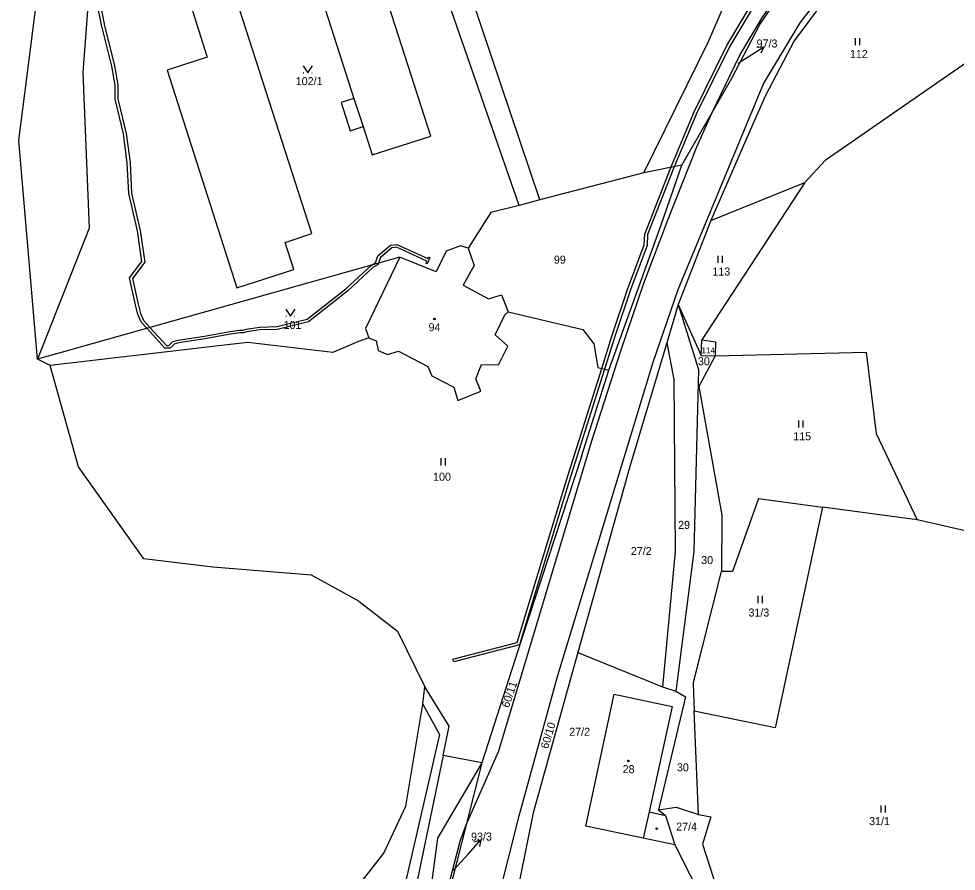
# Model space of a CAD drawing. Extents: x -670359 to -660124, y -978807 to -970072.
# Drawn here: x -670303.1 to -670103.9, y -977465.8 to -977284.7 of the extents above; entities that cross this region are included whole.
import ezdxf

# ---------------------------------------------------------------- set-up
doc = ezdxf.new("R2010")
doc.units = 0
for name, color, linetype in [('Hranice kat_území', 7, 'Continuous'), ('Hranice parcel', 7, 'Continuous'), ('Parcelní čísla', 7, 'Continuous'), ('Vnitřní kresba', 7, 'Continuous'), ('Věcná břemena k části', 7, 'Continuous'), ('Značky budov', 7, 'Continuous'), ('Značky kultur', 7, 'Continuous')]:
    doc.layers.add(name, color=color, linetype=linetype)

msp = doc.modelspace()

# ---------------------------------------------------------------- linework, layer by layer
at = {"layer": 'Hranice kat_území'}
for points in [[(-670303.09, -977310.58), (-670295.8, -977253.36)], [(-670299.11, -977356.99), (-670303.09, -977310.58)], [(-670296.4, -977358.37), (-670299.11, -977356.99)], [(-670290.39, -977379.85), (-670296.4, -977358.37)], [(-670276.51, -977399.38), (-670290.39, -977379.85)], [(-670261.89, -977401.16), (-670276.51, -977399.38)], [(-670240.86, -977402.91), (-670261.89, -977401.16)], [(-670230.82, -977408.42), (-670240.86, -977402.91)], [(-670230.82, -977408.42), (-670222.62, -977414.79)], [(-670222.62, -977414.79), (-670216.78, -977426.59)], [(-670217.21, -977430.27), (-670216.78, -977426.59)], [(-670220.88, -977451.91), (-670217.21, -977430.27)], [(-670225.52, -977461.96), (-670220.88, -977451.91)], [(-670231.74, -977469.91), (-670225.52, -977461.96)]]:
    msp.add_lwpolyline(points, dxfattribs=at)
at = {"layer": 'Hranice parcel'}
for points in [[(-670192.35, -977323.19), (-670223.53, -977230.71)], [(-670196.76, -977324.36), (-670228.36, -977233.44)], [(-670206.03, -977490.9), (-670201.37, -977472.26), (-670196.78, -977453.99), (-670188.6, -977424.41), (-670168.29, -977357.64), (-670162.97, -977342.22), (-670144.87, -977298.55), (-670137.06, -977285.54), (-670128.3, -977274.09), (-670118, -977262.95), (-670116.3, -977261.29)], [(-670215.56, -977309.6), (-670228.65, -977268.92)], [(-670155.78, -977304.6), (-670149.86, -977292.46), (-670145.08, -977284.34), (-670139.87, -977276.96), (-670134.89, -977270.75), (-670132.18, -977267.78)], [(-670122.33, -977267.85), (-670138.33, -977289.41)], [(-670241.01, -977273.11), (-670231.87, -977301.63)], [(-670145.67, -977285.92), (-670138.88, -977275.97)], [(-670240.8, -977330.34), (-670257.55, -977278.44)], [(-670266.7, -977281.45), (-670263.03, -977292.85)], [(-670087.08, -977283.85), (-670131.79, -977314.81)], [(-670151.59, -977297.32), (-670145.67, -977285.92)], [(-670138.33, -977289.41), (-670144.5, -977301.13)], [(-670263.03, -977292.85), (-670271.59, -977295.6)], [(-670271.59, -977295.6), (-670256.75, -977341.84)], [(-670155.78, -977304.6), (-670151.59, -977297.32)], [(-670144.5, -977301.13), (-670148.4, -977309.98)], [(-670231.87, -977301.63), (-670234.57, -977302.49)], [(-670234.57, -977302.49), (-670232.66, -977308.47)], [(-670201.12, -977440.18), (-670181.39, -977374.59), (-670175.18, -977355.21), (-670170.26, -977340.86), (-670165.11, -977327.29), (-670159.02, -977311.91), (-670155.78, -977304.6)], [(-670162.21, -977315.8), (-670155.78, -977304.6)], [(-670232.66, -977308.47), (-670229.95, -977307.6)], [(-670229.95, -977307.6), (-670228.02, -977313.62)], [(-670228.02, -977313.62), (-670215.56, -977309.6)], [(-670148.4, -977309.98), (-670156.05, -977327.52)], [(-670131.79, -977314.81), (-670136.07, -977319.5)], [(-670170.3, -977317.45), (-670192.35, -977323.19)], [(-670162.21, -977315.8), (-670170.3, -977317.45)], [(-670166.62, -977328.49), (-670162.21, -977315.8)], [(-670136.07, -977319.5), (-670157.98, -977352.9)], [(-670156.05, -977327.52), (-670136.07, -977319.5)], [(-670192.35, -977323.19), (-670196.76, -977324.36)], [(-670196.76, -977324.36), (-670202.77, -977325.83)], [(-670202.77, -977325.83), (-670207.63, -977333.4)], [(-670177.7, -977359.35), (-670166.62, -977328.49)], [(-670156.05, -977327.52), (-670162.98, -977345.39)], [(-670246.48, -977332.24), (-670240.8, -977330.34)], [(-670244.64, -977337.96), (-670246.48, -977332.24)], [(-670209.23, -977332.91), (-670212.28, -977334.09)], [(-670207.63, -977333.4), (-670209.23, -977332.91)], [(-670207.63, -977333.4), (-670206.3, -977337.09)], [(-670222.13, -977335.3), (-670299.11, -977356.99)], [(-670222.13, -977335.3), (-670229.44, -977350.52)], [(-670214.39, -977338.47), (-670222.13, -977335.3)], [(-670212.28, -977334.09), (-670214.39, -977338.47)], [(-670206.3, -977337.09), (-670208.65, -977341.31)], [(-670256.75, -977341.84), (-670244.64, -977337.96)], [(-670208.65, -977341.31), (-670203.31, -977344.15)], [(-670203.31, -977344.15), (-670200.5, -977343.37)], [(-670200.5, -977343.37), (-670199.08, -977346.97)], [(-670199.85, -977347.6), (-670199.08, -977346.97)], [(-670199.08, -977346.97), (-670183.27, -977350.68)], [(-670162.98, -977345.39), (-670165.4, -977353.5)], [(-670162.98, -977345.39), (-670158.68, -977359.17)], [(-670162.98, -977345.39), (-670158.11, -977356.19)], [(-670201.84, -977351.83), (-670199.85, -977347.6)], [(-670229.44, -977350.52), (-670228.7, -977352.45)], [(-670183.27, -977350.68), (-670180.89, -977353.74)], [(-670230.9, -977353.23), (-670236.36, -977355.59)], [(-670228.7, -977352.45), (-670230.9, -977353.23)], [(-670228.7, -977352.45), (-670227.14, -977353.1)], [(-670227.14, -977353.1), (-670226.75, -977355.18)], [(-670199.19, -977354.25), (-670201.84, -977351.83)], [(-670158.11, -977356.19), (-670157.98, -977352.9)], [(-670157.98, -977352.9), (-670155.03, -977353.34)], [(-670155.03, -977353.34), (-670155.15, -977356.3)], [(-670260.03, -977354.07), (-670296.4, -977358.37)], [(-670254.43, -977353.47), (-670260.03, -977354.07)], [(-670236.36, -977355.59), (-670254.43, -977353.47)], [(-670226.75, -977355.18), (-670224.76, -977355.99)], [(-670224.76, -977355.99), (-670222.43, -977355.29)], [(-670222.43, -977355.29), (-670216.21, -977358.53)], [(-670201.16, -977358.18), (-670199.19, -977354.25)], [(-670180.89, -977353.74), (-670180.04, -977358.78)], [(-670165.4, -977353.5), (-670173.4, -977380.26)], [(-670165.4, -977353.5), (-670163.9, -977361.3)], [(-670155.15, -977356.3), (-670158.63, -977362.77)], [(-670158.11, -977356.19), (-670155.15, -977356.3)], [(-670155.15, -977356.3), (-670123.04, -977355.5)], [(-670123.04, -977355.5), (-670120.93, -977372.79)], [(-670216.21, -977358.53), (-670215.35, -977360.54)], [(-670205.99, -977361.16), (-670204.77, -977358.13)], [(-670204.77, -977358.13), (-670201.16, -977358.18)], [(-670180.04, -977358.78), (-670177.7, -977359.35)], [(-670158.68, -977359.17), (-670159.68, -977397.88)], [(-670215.35, -977360.54), (-670210.64, -977362.97)], [(-670204.89, -977363.81), (-670205.99, -977361.16)], [(-670183.5, -977377.7), (-670177.7, -977359.35)], [(-670163.9, -977361.3), (-670163.6, -977397.85)], [(-670210.64, -977362.97), (-670209.78, -977365.77)], [(-670158.63, -977362.77), (-670153.7, -977390.16)], [(-670209.78, -977365.77), (-670204.89, -977363.81)], [(-670120.93, -977372.79), (-670112.18, -977391.09)], [(-670183.5, -977377.7), (-670196.38, -977416.73)], [(-670173.4, -977380.26), (-670184.32, -977419.3)], [(-670145.91, -977386.61), (-670151.47, -977402.09)], [(-670145.91, -977386.61), (-670132.35, -977388.41)], [(-670132.35, -977388.41), (-670142.37, -977435.34)], [(-670112.18, -977391.09), (-670132.35, -977388.41)], [(-670153.7, -977390.16), (-670153.79, -977402.08)], [(-670099.79, -977393.97), (-670112.18, -977391.09)], [(-670163.6, -977397.85), (-670166.29, -977426.62)], [(-670159.68, -977397.88), (-670163.49, -977427.52)], [(-670159.8, -977425.95), (-670153.79, -977402.08)], [(-670151.47, -977402.09), (-670153.79, -977402.08)], [(-670196.38, -977416.73), (-670204.73, -977442.75)], [(-670184.32, -977419.3), (-670193.77, -977453.38)], [(-670211.64, -977434.94), (-670216.78, -977426.59)], [(-670166.29, -977426.62), (-670163.49, -977427.52)], [(-670159.8, -977425.95), (-670159.56, -977431.74)], [(-670182.58, -977456.18), (-670176.62, -977428.15)], [(-670176.62, -977428.15), (-670164.24, -977430.8)], [(-670161.42, -977428.74), (-670167.19, -977452.69)], [(-670163.49, -977427.52), (-670161.42, -977428.74)], [(-670217.21, -977430.27), (-670213.73, -977436.69)], [(-670164.24, -977430.8), (-670169.12, -977453.16)], [(-670158.64, -977453.71), (-670159.56, -977431.74)], [(-670142.37, -977435.34), (-670159.56, -977431.74)], [(-670212.89, -977441.17), (-670211.64, -977434.94)], [(-670213.73, -977436.69), (-670222.65, -977475.42)], [(-670208.06, -977455.88), (-670201.12, -977440.18)], [(-670212.89, -977441.17), (-670220.34, -977477.03)], [(-670204.73, -977442.75), (-670212.89, -977441.17)], [(-670204.73, -977442.75), (-670208.06, -977455.88)], [(-670167.19, -977452.69), (-670163.43, -977452.16)], [(-670167.19, -977452.69), (-670165.68, -977453.9)], [(-670163.43, -977452.16), (-670158.64, -977453.71)], [(-670193.77, -977453.38), (-670198.08, -977474.39)], [(-670169.12, -977453.16), (-670165.68, -977453.9)], [(-670165.68, -977453.9), (-670163.73, -977460.15)], [(-670158.64, -977453.71), (-670156.08, -977454.21)], [(-670156.08, -977454.21), (-670157.8, -977460.03)], [(-670213.69, -977478.11), (-670213.16, -977474.17), (-670209.3, -977459.37), (-670208.06, -977455.88)], [(-670208.06, -977455.88), (-670213.69, -977478.11)], [(-670170.44, -977458.74), (-670182.58, -977456.18)], [(-670163.73, -977460.15), (-670170.44, -977458.74)], [(-670163.73, -977460.15), (-670147.24, -977492.66)], [(-670157.8, -977460.03), (-670147.24, -977492.66)]]:
    msp.add_lwpolyline(points, dxfattribs=at)
at = {"layer": 'Parcelní čísla'}
for p, q in [((-670146.26, -977290.72), (-670144.76, -977290.66)), ((-670150.24, -977294.11), (-670148.15, -977292.79)), ((-670206.32, -977459.53), (-670204.89, -977459.06)), ((-670210.77, -977465.62), (-670207.56, -977462.04))]:
    msp.add_line(p, q, dxfattribs=at)
for points in [[(-670148.15, -977292.79), (-670144.76, -977290.66), (-670145.46, -977291.99)], [(-670207.56, -977462.04), (-670204.89, -977459.06), (-670205.2, -977460.53)]]:
    msp.add_lwpolyline(points, dxfattribs=at)
at = {"layer": 'Vnitřní kresba'}
for points in [[(-670287.45, -977268.85), (-670289.49, -977296.13)], [(-670156.58, -977289.53), (-670149.5, -977273.26)], [(-670170.3, -977317.45), (-670156.58, -977289.53)], [(-670289.49, -977296.13), (-670288.11, -977329.15)], [(-670231.87, -977301.63), (-670229.95, -977307.6)], [(-670288.11, -977329.15), (-670299.11, -977356.99)], [(-670184.32, -977419.3), (-670166.29, -977426.62)], [(-670204.73, -977442.75), (-670214.13, -977458.76)], [(-670169.12, -977453.16), (-670170.44, -977458.74)], [(-670214.13, -977458.76), (-670216, -977473.14)]]:
    msp.add_lwpolyline(points, dxfattribs=at)
at = {"layer": 'Věcná břemena k části'}
for points in [[(-670285.47, -977286.29), (-670287.13, -977278.03)], [(-670286.53, -977277.95), (-670284.89, -977286.15)], [(-670196.68, -977417.66), (-670210.67, -977421.31), (-670210.84, -977420.73), (-670197.18, -977417.17), (-670192.02, -977400.14), (-670186.71, -977382.7), (-670179.22, -977358.98), (-670176.99, -977351.89), (-670173.77, -977342.22), (-670170.19, -977332.73), (-670170.1, -977330.42), (-670164.54, -977316.27), (-670159.57, -977304.43), (-670152.64, -977290.41), (-670147.04, -977281.03)], [(-670146.54, -977281.35), (-670152.12, -977290.69), (-670159.03, -977304.67), (-670163.84, -977316.13), (-670169.5, -977330.54), (-670169.59, -977332.85), (-670173.06, -977342.07), (-670176.38, -977351.98), (-670178.64, -977359.12), (-670186.13, -977382.88), (-670191.44, -977400.32), (-670196.68, -977417.66)], [(-670283.31, -977294.8), (-670285.47, -977286.29)], [(-670284.89, -977286.15), (-670282.73, -977294.68)], [(-670282.61, -977298.79), (-670283.31, -977294.8)], [(-670282.73, -977294.68), (-670282.01, -977298.73)], [(-670282.61, -977301.76), (-670282.61, -977298.79)], [(-670282.01, -977298.73), (-670282.01, -977301.68)], [(-670280.84, -977309.17), (-670282.61, -977301.76)], [(-670282.01, -977301.68), (-670280.24, -977309.07)], [(-670280.05, -977315.27), (-670280.84, -977309.17)], [(-670280.24, -977309.07), (-670279.45, -977315.21)], [(-670279.7, -977321.84), (-670280.05, -977315.27)], [(-670279.45, -977315.21), (-670279.1, -977321.76)], [(-670277.88, -977329.76), (-670279.7, -977321.84)], [(-670279.1, -977321.76), (-670277.28, -977329.64)], [(-670276.92, -977336.22), (-670277.88, -977329.76)], [(-670277.28, -977329.64), (-670276.28, -977336.38)], [(-670226.78, -977335.04), (-670224.09, -977332.75)], [(-670223.85, -977333.33), (-670226.26, -977335.4)], [(-670224.09, -977332.75), (-670222.73, -977332.61)], [(-670222.83, -977333.23), (-670223.85, -977333.33)], [(-670216.41, -977336.19), (-670222.83, -977333.23)], [(-670222.73, -977332.61), (-670216.19, -977335.63)], [(-670227.32, -977336.57), (-670226.78, -977335.04)], [(-670226.26, -977335.4), (-670226.69, -977336.59)], [(-670215.78, -977335.4), (-670216.32, -977336.74)], [(-670216.19, -977335.63), (-670216.06, -977335.29)], [(-670216.06, -977335.29), (-670215.78, -977335.4)], [(-670279.59, -977339.7), (-670276.92, -977336.22)], [(-670276.28, -977336.38), (-670278.95, -977339.84)], [(-670233.57, -977342.03), (-670228.18, -977337)], [(-670228.18, -977337), (-670227.32, -977336.57)], [(-670226.84, -977336.99), (-670227.83, -977337.5)], [(-670226.69, -977336.59), (-670226.84, -977336.99)], [(-670216.59, -977336.63), (-670216.41, -977336.19)], [(-670216.32, -977336.74), (-670216.59, -977336.63)], [(-670227.83, -977337.5), (-670233.17, -977342.49)], [(-670278.31, -977345.47), (-670279.59, -977339.7)], [(-670278.95, -977339.84), (-670277.73, -977345.33)], [(-670241.8, -977348.51), (-670233.57, -977342.03)], [(-670233.17, -977342.49), (-670241.54, -977349.07)], [(-670277.73, -977345.33), (-670277.23, -977347.29)], [(-670277.79, -977347.49), (-670278.31, -977345.47)], [(-670277.23, -977347.29), (-670276.51, -977348.89)], [(-670277.01, -977349.23), (-670277.79, -977347.49)], [(-670275.89, -977350.45), (-670277.01, -977349.23)], [(-670276.51, -977348.89), (-670275.24, -977350.26)], [(-670248.26, -977350.08), (-670241.8, -977348.51)], [(-670241.54, -977349.07), (-670248.18, -977350.68)], [(-670272.03, -977354.64), (-670275.89, -977350.45)], [(-670275.24, -977350.26), (-670271.69, -977354.12)], [(-670263.63, -977352.08), (-670258.62, -977351.18)], [(-670258.62, -977351.18), (-670256.16, -977350.82)], [(-670256.16, -977350.82), (-670255.48, -977350.84)], [(-670255.48, -977350.84), (-670254.76, -977350.6)], [(-670254.62, -977351.18), (-670255.38, -977351.44)], [(-670254.76, -977350.6), (-670251.88, -977350.2)], [(-670251.82, -977350.8), (-670254.62, -977351.18)], [(-670251.88, -977350.2), (-670248.26, -977350.08)], [(-670248.18, -977350.68), (-670251.82, -977350.8)], [(-670271.21, -977354.07), (-670270.34, -977353.24)], [(-670270.34, -977353.24), (-670269.21, -977352.97)], [(-670269.21, -977352.97), (-670263.63, -977352.08)], [(-670263.53, -977352.68), (-670269.09, -977353.55)], [(-670258.52, -977351.78), (-670263.53, -977352.68)], [(-670256.12, -977351.42), (-670258.52, -977351.78)], [(-670255.38, -977351.44), (-670256.12, -977351.42)], [(-670270.95, -977354.65), (-670272.03, -977354.64)], [(-670271.69, -977354.12), (-670271.21, -977354.07)], [(-670270.04, -977353.78), (-670270.95, -977354.65)], [(-670269.09, -977353.55), (-670270.04, -977353.78)]]:
    msp.add_lwpolyline(points, dxfattribs=at)
at = {"layer": 'Značky budov'}
for centre in [(-670214.77, -977348.47), (-670173.58, -977442.33)]:
    msp.add_circle(centre, 0.175, dxfattribs=at)
at = {"layer": 'Značky kultur'}
for p, q in [((-670125.37, -977288.84), (-670125.37, -977290.34)), ((-670124.37, -977290.34), (-670124.37, -977288.84)), ((-670242.64, -977296.2), (-670242.54, -977296.2)), ((-670240.84, -977296.2), (-670240.74, -977296.2)), ((-670154.58, -977335.04), (-670154.58, -977336.54)), ((-670153.58, -977336.54), (-670153.58, -977335.04)), ((-670246.32, -977347.89), (-670246.22, -977347.89)), ((-670244.52, -977347.89), (-670244.42, -977347.89)), ((-670137.4, -977370.02), (-670137.4, -977371.52)), ((-670136.4, -977371.52), (-670136.4, -977370.02)), ((-670213.45, -977378.06), (-670213.45, -977379.56)), ((-670212.45, -977379.56), (-670212.45, -977378.06)), ((-670146.1, -977407.29), (-670146.1, -977408.79)), ((-670145.1, -977408.79), (-670145.1, -977407.29)), ((-670119.91, -977451.78), (-670119.91, -977453.28)), ((-670118.91, -977453.28), (-670118.91, -977451.78))]:
    msp.add_line(p, q, dxfattribs=at)
for points in [[(-670242.69, -977294.7), (-670241.69, -977296.2), (-670240.69, -977294.7)], [(-670246.37, -977346.39), (-670245.37, -977347.89), (-670244.37, -977346.39)]]:
    msp.add_lwpolyline(points, dxfattribs=at)
for centre in [(-670214.77, -977348.47), (-670173.58, -977442.33), (-670167.57, -977456.73)]:
    msp.add_circle(centre, 0.175, dxfattribs=at)

# ---------------------------------------------------------------- texts
at = {"layer": 'Parcelní čísla'}
for s, height, p in [('97/3', 1.7, (-670146.33, -977290.8)), ('112', 1.7, (-670126.51, -977293.04)), ('97/3', 0.1, (-670150.4, -977294.11)), ('102/1', 1.7, (-670244.24, -977298.8)), ('99', 1.7, (-670189.4, -977336.71)), ('113', 1.7, (-670155.72, -977339.24)), ('101', 1.7, (-670246.83, -977350.59)), ('94', 1.7, (-670216.02, -977351.07)), ('114', 1.27, (-670158.04, -977355.78)), ('30', 1.7, (-670158.8, -977358.29)), ('115', 1.7, (-670138.54, -977374.22)), ('100', 1.7, (-670215.06, -977382.82)), ('29', 1.7, (-670163, -977393.04)), ('27/2', 1.7, (-670173.05, -977398.6)), ('30', 1.7, (-670158.1, -977400.52)), ('31/3', 1.7, (-670148.06, -977411.66)), ('27/2', 1.7, (-670186.14, -977436.99)), ('30', 1.7, (-670163.26, -977444.54)), ('28', 1.7, (-670174.79, -977444.93)), ('31/1', 1.7, (-670122.42, -977455.97)), ('27/4', 1.7, (-670163.41, -977457.14)), ('93/3', 1.7, (-670207, -977459.25)), ('93/3', 0.1, (-670210.93, -977465.62))]:
    msp.add_text(s, height=height, dxfattribs=at).set_placement(p)
for s, rotation, p in [('60/11', 71.231, (-670198.98, -977431.16)), ('60/10', 73.1498, (-670190.63, -977439.88))]:
    msp.add_text(s, height=1.7, rotation=rotation, dxfattribs=at).set_placement(p)

doc.saveas('drawing.dxf')
